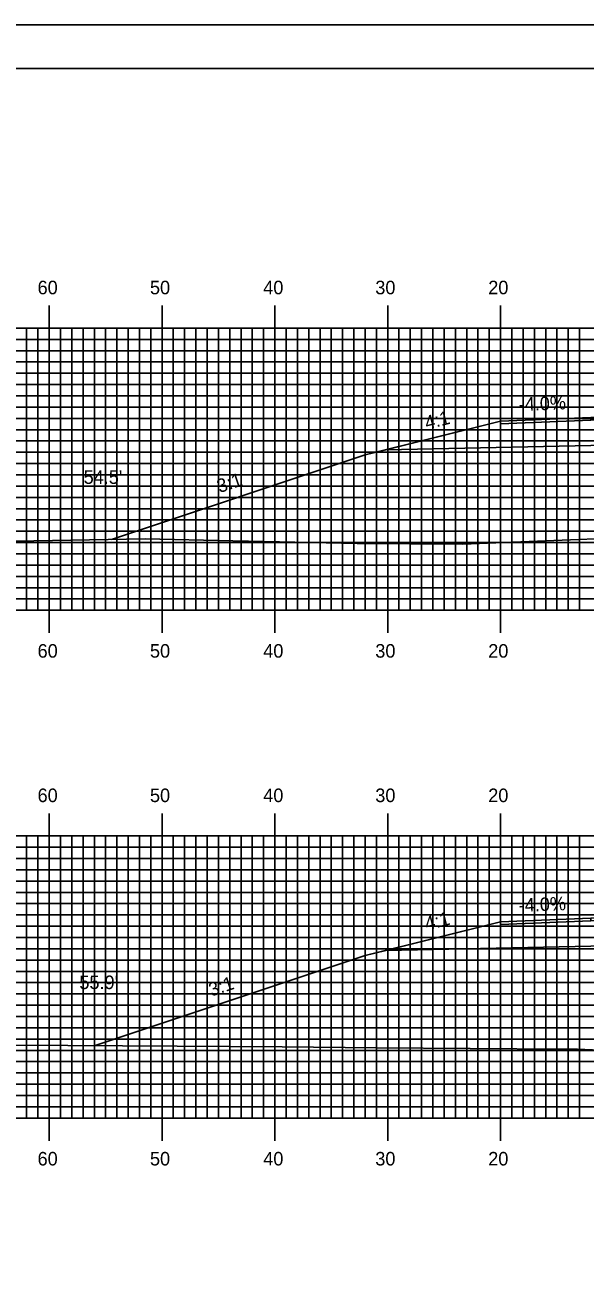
# Model space of a CAD drawing. Extents: x 1818850 to 1819194, y 442591 to 442811.
# Drawn here: x 1818954 to 1819003.7, y 442700.5 to 442810.5 of the extents above; entities that cross this region are included whole.
import ezdxf

# ---------------------------------------------------------------- set-up
doc = ezdxf.new("R2010")
doc.units = 0
for name, color, linetype in [('ANNOTATION', 7, 'Continuous'), ('BORDER', 7, 'Continuous'), ('D_Roadway_Centerline', 7, 'Continuous'), ('D_Roadway_Edge_Shoulder', 7, 'Continuous'), ('D_Roadway_SlopeLines', 7, 'Continuous'), ('D_Roadway_SubGrade', 7, 'Continuous'), ('D_Text_Standard', 7, 'Continuous'), ('H_V ANNOTATION', 7, 'Continuous'), ('MAJOR', 7, 'Continuous'), ('MINOR', 7, 'Continuous'), ('PLOT BOUNDARY', 7, 'Continuous'), ('S_Roadway_Centerline', 7, 'Continuous')]:
    doc.layers.add(name, color=color, linetype=linetype)

msp = doc.modelspace()

# ---------------------------------------------------------------- linework, layer by layer
at = {"layer": 'BORDER'}
msp.add_lwpolyline([(1818866.55, 442596.67), (1819186.55, 442596.67), (1819186.55, 442806.67), (1818866.55, 442806.67)], close=True, dxfattribs=at)
at = {"layer": 'D_Roadway_Centerline'}
for points in [[(1818961.68, 442764.95), (1818984.15, 442772.44), (1818985.98, 442772.9), (1818996.15, 442775.44), (1819004.15, 442775.76), (1819016.15, 442776), (1819028.15, 442775.76), (1819036.15, 442775.44), (1819046.33, 442772.9), (1819048.15, 442772.44), (1819070.66, 442764.94)], [(1818960.21, 442720.09), (1818984.15, 442728.07), (1818985.98, 442728.52), (1818996.15, 442731.07), (1819004.15, 442731.39), (1819016.15, 442731.63), (1819028.15, 442731.39), (1819036.15, 442731.07), (1819046.33, 442728.52), (1819048.15, 442728.07), (1819066.99, 442721.79)]]:
    msp.add_lwpolyline(points, dxfattribs=at)
at = {"layer": 'D_Roadway_Edge_Shoulder'}
for points in [[(1819004.15, 442775.76), (1818996.15, 442775.44), (1818996.15, 442775.19), (1819004.15, 442775.51)], [(1819004.15, 442731.39), (1818996.15, 442731.07), (1818996.15, 442730.82), (1819004.15, 442731.14)]]:
    msp.add_lwpolyline(points, close=True, dxfattribs=at)
at = {"layer": 'D_Roadway_SlopeLines'}
for points in [[(1818996.15, 442775.44), (1818984.15, 442772.44), (1818961.68, 442764.95)], [(1818996.15, 442731.07), (1818984.15, 442728.07), (1818960.21, 442720.09)]]:
    msp.add_lwpolyline(points, dxfattribs=at)
at = {"layer": 'D_Roadway_SubGrade'}
for points in [[(1819004.15, 442773.26), (1818985.98, 442772.9), (1818996.15, 442775.44), (1818996.15, 442775.19), (1819004.15, 442775.51), (1819016.15, 442775.75), (1819028.15, 442775.51), (1819036.15, 442775.19), (1819036.15, 442775.44), (1819046.33, 442772.9), (1819028.15, 442773.26), (1819016.15, 442773.5)], [(1819004.15, 442728.89), (1818985.98, 442728.52), (1818996.15, 442731.07), (1818996.15, 442730.82), (1819004.15, 442731.14), (1819016.15, 442731.38), (1819028.15, 442731.14), (1819036.15, 442730.82), (1819036.15, 442731.07), (1819046.33, 442728.52), (1819028.15, 442728.89), (1819016.15, 442729.13)]]:
    msp.add_lwpolyline(points, close=True, dxfattribs=at)
at = {"layer": 'MAJOR'}
for p, q in [((1818956.15, 442785.67), (1818956.15, 442783.67)), ((1818966.15, 442785.67), (1818966.15, 442783.67)), ((1818976.15, 442785.67), (1818976.15, 442783.67)), ((1818986.15, 442785.67), (1818986.15, 442783.67)), ((1818996.15, 442785.67), (1818996.15, 442783.67)), ((1818876.15, 442783.67), (1819156.15, 442783.67)), ((1818876.15, 442783.67), (1819156.15, 442783.67)), ((1818956.15, 442758.67), (1818956.15, 442783.67)), ((1818966.15, 442758.67), (1818966.15, 442783.67)), ((1818976.15, 442758.67), (1818976.15, 442783.67)), ((1818986.15, 442758.67), (1818986.15, 442783.67)), ((1818996.15, 442758.67), (1818996.15, 442783.67)), ((1818876.15, 442778.67), (1819156.15, 442778.67)), ((1818876.15, 442773.67), (1819156.15, 442773.67)), ((1818876.15, 442768.67), (1819156.15, 442768.67)), ((1818876.15, 442763.67), (1819156.15, 442763.67)), ((1818876.15, 442758.67), (1819156.15, 442758.67)), ((1818876.15, 442758.67), (1819156.15, 442758.67)), ((1818956.15, 442756.66), (1818956.15, 442758.67)), ((1818966.15, 442756.66), (1818966.15, 442758.67)), ((1818976.15, 442756.66), (1818976.15, 442758.67)), ((1818986.15, 442756.66), (1818986.15, 442758.67)), ((1818996.15, 442756.66), (1818996.15, 442758.67)), ((1818956.15, 442740.67), (1818956.15, 442738.67)), ((1818966.15, 442740.67), (1818966.15, 442738.67)), ((1818976.15, 442740.67), (1818976.15, 442738.67)), ((1818986.15, 442740.67), (1818986.15, 442738.67)), ((1818996.15, 442740.67), (1818996.15, 442738.67)), ((1818876.15, 442738.67), (1819156.15, 442738.67)), ((1818876.15, 442738.67), (1819156.15, 442738.67)), ((1818956.15, 442713.67), (1818956.15, 442738.67)), ((1818966.15, 442713.67), (1818966.15, 442738.67)), ((1818976.15, 442713.67), (1818976.15, 442738.67)), ((1818986.15, 442713.67), (1818986.15, 442738.67)), ((1818996.15, 442713.67), (1818996.15, 442738.67)), ((1818876.15, 442733.67), (1819156.15, 442733.67)), ((1818876.15, 442728.67), (1819156.15, 442728.67)), ((1818876.15, 442723.67), (1819156.15, 442723.67)), ((1818876.15, 442718.67), (1819156.15, 442718.67)), ((1818876.15, 442713.67), (1819156.15, 442713.67)), ((1818876.15, 442713.67), (1819156.15, 442713.67)), ((1818956.15, 442711.66), (1818956.15, 442713.67)), ((1818966.15, 442711.66), (1818966.15, 442713.67)), ((1818976.15, 442711.66), (1818976.15, 442713.67)), ((1818986.15, 442711.66), (1818986.15, 442713.67)), ((1818996.15, 442711.66), (1818996.15, 442713.67))]:
    msp.add_line(p, q, dxfattribs=at)
at = {"layer": 'MINOR'}
for p, q in [((1818954.15, 442758.67), (1818954.15, 442783.67)), ((1818955.15, 442758.67), (1818955.15, 442783.67)), ((1818957.15, 442758.67), (1818957.15, 442783.67)), ((1818958.15, 442758.67), (1818958.15, 442783.67)), ((1818959.15, 442758.67), (1818959.15, 442783.67)), ((1818960.15, 442758.67), (1818960.15, 442783.67)), ((1818961.15, 442758.67), (1818961.15, 442783.67)), ((1818962.15, 442758.67), (1818962.15, 442783.67)), ((1818963.15, 442758.67), (1818963.15, 442783.67)), ((1818964.15, 442758.67), (1818964.15, 442783.67)), ((1818965.15, 442758.67), (1818965.15, 442783.67)), ((1818967.15, 442758.67), (1818967.15, 442783.67)), ((1818968.15, 442758.67), (1818968.15, 442783.67)), ((1818969.15, 442758.67), (1818969.15, 442783.67)), ((1818970.15, 442758.67), (1818970.15, 442783.67)), ((1818971.15, 442758.67), (1818971.15, 442783.67)), ((1818972.15, 442758.67), (1818972.15, 442783.67)), ((1818973.15, 442758.67), (1818973.15, 442783.67)), ((1818974.15, 442758.67), (1818974.15, 442783.67)), ((1818975.15, 442758.67), (1818975.15, 442783.67)), ((1818977.15, 442758.67), (1818977.15, 442783.67)), ((1818978.15, 442758.67), (1818978.15, 442783.67)), ((1818979.15, 442758.67), (1818979.15, 442783.67)), ((1818980.15, 442758.67), (1818980.15, 442783.67)), ((1818981.15, 442758.67), (1818981.15, 442783.67)), ((1818982.15, 442758.67), (1818982.15, 442783.67)), ((1818983.15, 442758.67), (1818983.15, 442783.67)), ((1818984.15, 442758.67), (1818984.15, 442783.67)), ((1818985.15, 442758.67), (1818985.15, 442783.67)), ((1818987.15, 442758.67), (1818987.15, 442783.67)), ((1818988.15, 442758.67), (1818988.15, 442783.67)), ((1818989.15, 442758.67), (1818989.15, 442783.67)), ((1818990.15, 442758.67), (1818990.15, 442783.67)), ((1818991.15, 442758.67), (1818991.15, 442783.67)), ((1818992.15, 442758.67), (1818992.15, 442783.67)), ((1818993.15, 442758.67), (1818993.15, 442783.67)), ((1818994.15, 442758.67), (1818994.15, 442783.67)), ((1818995.15, 442758.67), (1818995.15, 442783.67)), ((1818997.15, 442758.67), (1818997.15, 442783.67)), ((1818998.15, 442758.67), (1818998.15, 442783.67)), ((1818999.15, 442758.67), (1818999.15, 442783.67)), ((1819000.15, 442758.67), (1819000.15, 442783.67)), ((1819001.15, 442758.67), (1819001.15, 442783.67)), ((1819002.15, 442758.67), (1819002.15, 442783.67)), ((1819003.15, 442758.67), (1819003.15, 442783.67)), ((1818876.15, 442782.67), (1819156.15, 442782.67)), ((1818876.15, 442781.67), (1819156.15, 442781.67)), ((1818876.15, 442780.67), (1819156.15, 442780.67)), ((1818876.15, 442779.67), (1819156.15, 442779.67)), ((1818876.15, 442777.67), (1819156.15, 442777.67)), ((1818876.15, 442776.67), (1819156.15, 442776.67)), ((1818876.15, 442775.67), (1819156.15, 442775.67)), ((1818876.15, 442774.67), (1819156.15, 442774.67)), ((1818876.15, 442772.67), (1819156.15, 442772.67)), ((1818876.15, 442771.67), (1819156.15, 442771.67)), ((1818876.15, 442770.67), (1819156.15, 442770.67)), ((1818876.15, 442769.67), (1819156.15, 442769.67)), ((1818876.15, 442767.67), (1819156.15, 442767.67)), ((1818876.15, 442766.67), (1819156.15, 442766.67)), ((1818876.15, 442765.67), (1819156.15, 442765.67)), ((1818876.15, 442764.67), (1819156.15, 442764.67)), ((1818876.15, 442762.67), (1819156.15, 442762.67)), ((1818876.15, 442761.67), (1819156.15, 442761.67)), ((1818876.15, 442760.67), (1819156.15, 442760.67)), ((1818876.15, 442759.67), (1819156.15, 442759.67)), ((1818954.15, 442713.67), (1818954.15, 442738.67)), ((1818955.15, 442713.67), (1818955.15, 442738.67)), ((1818957.15, 442713.67), (1818957.15, 442738.67)), ((1818958.15, 442713.67), (1818958.15, 442738.67)), ((1818959.15, 442713.67), (1818959.15, 442738.67)), ((1818960.15, 442713.67), (1818960.15, 442738.67)), ((1818961.15, 442713.67), (1818961.15, 442738.67)), ((1818962.15, 442713.67), (1818962.15, 442738.67)), ((1818963.15, 442713.67), (1818963.15, 442738.67)), ((1818964.15, 442713.67), (1818964.15, 442738.67)), ((1818965.15, 442713.67), (1818965.15, 442738.67)), ((1818967.15, 442713.67), (1818967.15, 442738.67)), ((1818968.15, 442713.67), (1818968.15, 442738.67)), ((1818969.15, 442713.67), (1818969.15, 442738.67)), ((1818970.15, 442713.67), (1818970.15, 442738.67)), ((1818971.15, 442713.67), (1818971.15, 442738.67)), ((1818972.15, 442713.67), (1818972.15, 442738.67)), ((1818973.15, 442713.67), (1818973.15, 442738.67)), ((1818974.15, 442713.67), (1818974.15, 442738.67)), ((1818975.15, 442713.67), (1818975.15, 442738.67)), ((1818977.15, 442713.67), (1818977.15, 442738.67)), ((1818978.15, 442713.67), (1818978.15, 442738.67)), ((1818979.15, 442713.67), (1818979.15, 442738.67)), ((1818980.15, 442713.67), (1818980.15, 442738.67)), ((1818981.15, 442713.67), (1818981.15, 442738.67)), ((1818982.15, 442713.67), (1818982.15, 442738.67)), ((1818983.15, 442713.67), (1818983.15, 442738.67)), ((1818984.15, 442713.67), (1818984.15, 442738.67)), ((1818985.15, 442713.67), (1818985.15, 442738.67)), ((1818987.15, 442713.67), (1818987.15, 442738.67)), ((1818988.15, 442713.67), (1818988.15, 442738.67)), ((1818989.15, 442713.67), (1818989.15, 442738.67)), ((1818990.15, 442713.67), (1818990.15, 442738.67)), ((1818991.15, 442713.67), (1818991.15, 442738.67)), ((1818992.15, 442713.67), (1818992.15, 442738.67)), ((1818993.15, 442713.67), (1818993.15, 442738.67)), ((1818994.15, 442713.67), (1818994.15, 442738.67)), ((1818995.15, 442713.67), (1818995.15, 442738.67)), ((1818997.15, 442713.67), (1818997.15, 442738.67)), ((1818998.15, 442713.67), (1818998.15, 442738.67)), ((1818999.15, 442713.67), (1818999.15, 442738.67)), ((1819000.15, 442713.67), (1819000.15, 442738.67)), ((1819001.15, 442713.67), (1819001.15, 442738.67)), ((1819002.15, 442713.67), (1819002.15, 442738.67)), ((1819003.15, 442713.67), (1819003.15, 442738.67)), ((1818876.15, 442737.67), (1819156.15, 442737.67)), ((1818876.15, 442736.67), (1819156.15, 442736.67)), ((1818876.15, 442735.67), (1819156.15, 442735.67)), ((1818876.15, 442734.67), (1819156.15, 442734.67)), ((1818876.15, 442732.67), (1819156.15, 442732.67)), ((1818876.15, 442731.67), (1819156.15, 442731.67)), ((1818876.15, 442730.67), (1819156.15, 442730.67)), ((1818876.15, 442729.67), (1819156.15, 442729.67)), ((1818876.15, 442727.67), (1819156.15, 442727.67)), ((1818876.15, 442726.67), (1819156.15, 442726.67)), ((1818876.15, 442725.67), (1819156.15, 442725.67)), ((1818876.15, 442724.67), (1819156.15, 442724.67)), ((1818876.15, 442722.67), (1819156.15, 442722.67)), ((1818876.15, 442721.67), (1819156.15, 442721.67)), ((1818876.15, 442720.67), (1819156.15, 442720.67)), ((1818876.15, 442719.67), (1819156.15, 442719.67)), ((1818876.15, 442717.67), (1819156.15, 442717.67)), ((1818876.15, 442716.67), (1819156.15, 442716.67)), ((1818876.15, 442715.67), (1819156.15, 442715.67)), ((1818876.15, 442714.67), (1819156.15, 442714.67))]:
    msp.add_line(p, q, dxfattribs=at)
at = {"layer": 'PLOT BOUNDARY'}
msp.add_lwpolyline([(1818850.36, 442590.55), (1819190.36, 442590.55), (1819190.36, 442810.55), (1818850.36, 442810.55)], close=True, dxfattribs=at)
at = {"layer": 'S_Roadway_Centerline'}
for points in [[(1818939.64, 442764.62), (1818954.8, 442764.81), (1818964.64, 442765.01), (1818972.42, 442764.82), (1818983.45, 442764.59), (1818992.8, 442764.53), (1819006, 442765.06), (1819019.6, 442764.63), (1819023.44, 442764.42), (1819029.47, 442764.33), (1819045.29, 442764.18), (1819056.55, 442764.44), (1819057.72, 442764.47), (1819070.3, 442764.93), (1819073.96, 442765.06)], [(1818876.15, 442719.62), (1818884.53, 442719.84), (1818887.7, 442719.84), (1818900.44, 442719.94), (1818909.33, 442720), (1818923.1, 442719.99), (1818940.8, 442720.11), (1818948.93, 442720.12), (1818952.95, 442720.12), (1818967.5, 442720.05), (1818976.8, 442719.99), (1818985.17, 442719.89), (1819001.76, 442719.77), (1819002.98, 442719.77), (1819004.96, 442719.69), (1819017.83, 442719.31), (1819032.61, 442719.27), (1819052.82, 442720.41), (1819068.74, 442721.96), (1819070.09, 442722.09), (1819098.53, 442725.38)]]:
    msp.add_lwpolyline(points, dxfattribs=at)

# ---------------------------------------------------------------- texts
at = {"layer": 'ANNOTATION'}
for s, rotation, p in [('-4.0%', 2.2906, (1818997.78, 442776.31)), ('4:1', 14.0362, (1818989.6, 442774.67)), ('3:1', 18.4348, (1818971.25, 442769.05)), ('-4.0%', 2.2906, (1818997.78, 442731.93)), ('4:1', 14.0362, (1818989.6, 442730.29)), ('3:1', 18.4348, (1818970.52, 442724.43))]:
    msp.add_text(s, height=1.2, rotation=rotation, dxfattribs=at).set_placement(p)
at = {"layer": 'D_Text_Standard'}
for s, p in [("54.5'", (1818959.2, 442769.87)), ("55.9'", (1818958.82, 442725.1))]:
    msp.add_text(s, height=1.2, dxfattribs=at).set_placement(p)
at = {"layer": 'H_V ANNOTATION'}
for s, p in [('60', (1818955.12, 442786.67)), ('50', (1818965.08, 442786.67)), ('40', (1818975.12, 442786.67)), ('30', (1818985.05, 442786.67)), ('20', (1818995.06, 442786.67)), ('60', (1818955.12, 442754.47)), ('50', (1818965.08, 442754.47)), ('40', (1818975.12, 442754.47)), ('30', (1818985.05, 442754.47)), ('20', (1818995.06, 442754.47)), ('60', (1818955.12, 442741.67)), ('50', (1818965.08, 442741.67)), ('40', (1818975.12, 442741.67)), ('30', (1818985.05, 442741.67)), ('20', (1818995.06, 442741.67)), ('60', (1818955.12, 442709.47)), ('50', (1818965.08, 442709.47)), ('40', (1818975.12, 442709.47)), ('30', (1818985.05, 442709.47)), ('20', (1818995.06, 442709.47))]:
    msp.add_text(s, height=1.2, dxfattribs=at).set_placement(p)

doc.saveas('drawing.dxf')
